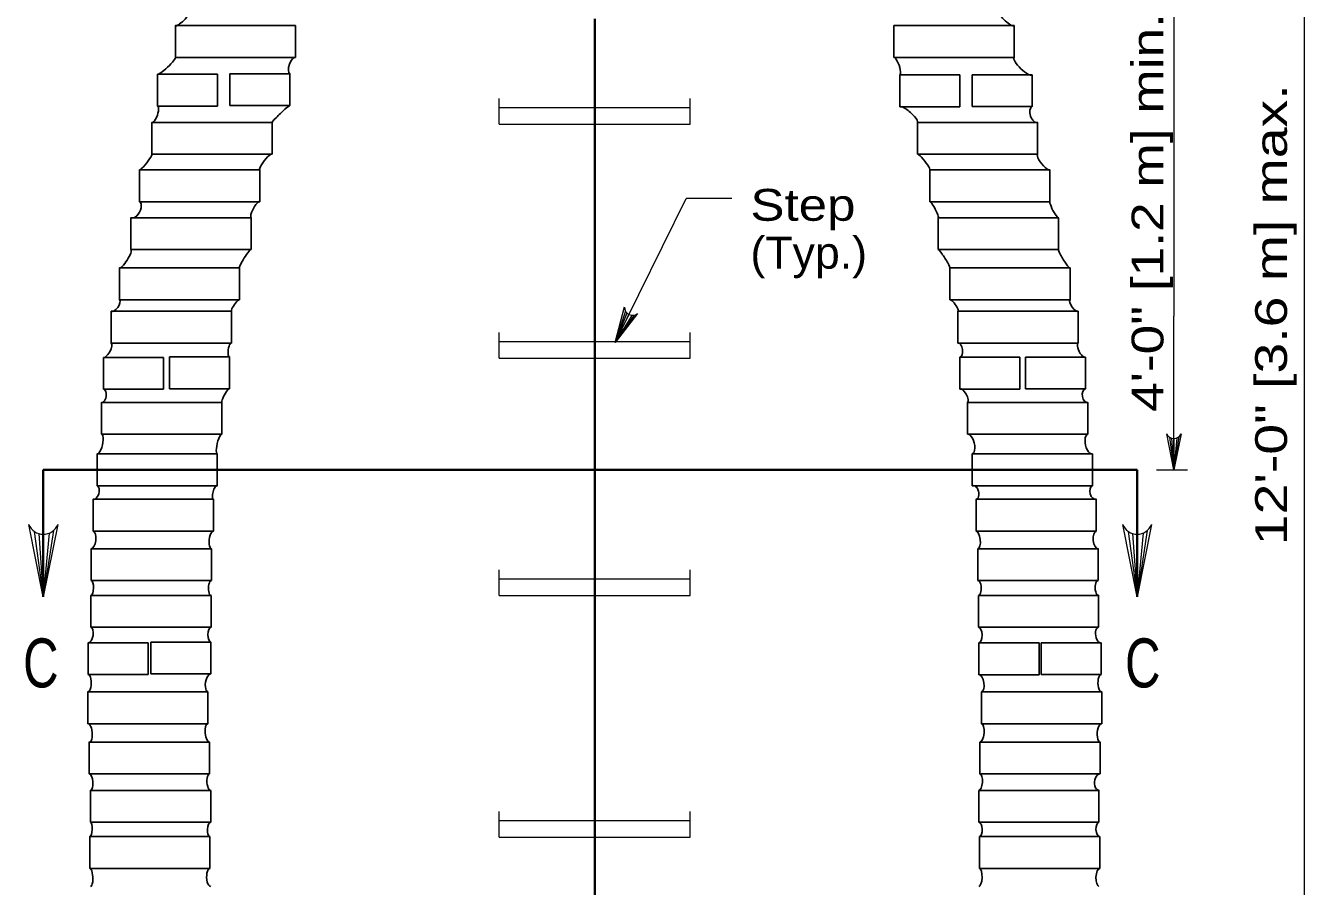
# Model space of a CAD drawing. Extents: x 1083.1 to 1117.1, y 697.4 to 741.4.
# Drawn here: x 1087.43 to 1093.7, y 732.34 to 736.56 of the extents above; entities that cross this region are included whole.
import ezdxf

# ---------------------------------------------------------------- set-up
doc = ezdxf.new("R2010")
doc.units = 0
doc.header["$LTSCALE"] = 0.062
doc.layers.add('1', color=7, linetype='Continuous', lineweight=13)

msp = doc.modelspace()

# ---------------------------------------------------------------- linework, layer by layer
at = {"layer": '1'}
for p, q in [((1093.70258, 733.89467), (1093.70258, 738.99733)), ((1093.06292, 738.25633), (1093.06292, 735.13425)), ((1089.75575, 736.07425), (1089.75575, 736.19958)), ((1089.75575, 736.15558), (1090.69217, 736.15558)), ((1090.69217, 736.07425), (1090.69217, 736.19958)), ((1089.75575, 736.07425), (1090.69217, 736.07425)), ((1090.32342, 735.00442), (1090.67242, 735.71092)), ((1090.89642, 735.71092), (1090.67242, 735.71092)), ((1090.37467, 735.15792), (1090.32342, 735.00442)), ((1090.38217, 735.14808), (1090.32342, 735.00442)), ((1090.39158, 735.14158), (1090.32342, 735.00442)), ((1090.41775, 735.13858), (1090.32342, 735.00442)), ((1090.40575, 735.13767), (1090.32342, 735.00442)), ((1093.06292, 734.38058), (1093.06292, 735.13425)), ((1089.75575, 734.92767), (1089.75575, 735.05292)), ((1090.69217, 734.92767), (1090.69217, 735.05292)), ((1089.75575, 735.009), (1090.69217, 735.009)), ((1089.75575, 734.92767), (1090.69217, 734.92767)), ((1093.0405, 734.54083), (1093.06292, 734.38058)), ((1093.05158, 734.53542), (1093.06292, 734.38058)), ((1093.08775, 734.54275), (1093.06292, 734.38058)), ((1093.07733, 734.53658), (1093.06292, 734.38058)), ((1093.06292, 734.53375), (1093.06292, 734.38058)), ((1092.97708, 734.38058), (1093.12975, 734.38058)), ((1087.47642, 734.07933), (1087.52125, 733.75883)), ((1087.57083, 734.08308), (1087.52125, 733.75883)), ((1092.83792, 734.07925), (1092.88275, 733.75883)), ((1092.93233, 734.08308), (1092.88275, 733.75883)), ((1087.49867, 734.0685), (1087.52125, 733.75883)), ((1087.55008, 734.07083), (1087.52125, 733.75883)), ((1087.52125, 734.06517), (1087.52125, 733.75883)), ((1092.86017, 734.06842), (1092.88275, 733.75883)), ((1092.91158, 734.07083), (1092.88275, 733.75883)), ((1092.88275, 734.06517), (1092.88275, 733.75883)), ((1089.75575, 733.76483), (1089.75575, 733.89017)), ((1090.69217, 733.76483), (1090.69217, 733.89017)), ((1093.70258, 730.36367), (1093.70258, 733.89467)), ((1089.75575, 733.84625), (1090.69217, 733.84625)), ((1089.75575, 733.76483), (1090.69217, 733.76483)), ((1089.75575, 732.58133), (1089.75575, 732.70667)), ((1090.69217, 732.58133), (1090.69217, 732.70667)), ((1089.75575, 732.66267), (1090.69217, 732.66267)), ((1089.75575, 732.58133), (1090.69217, 732.58133))]:
    msp.add_line(p, q, dxfattribs=at)
at = {"layer": '1', "lineweight": 35}
for p, q in [((1090.224, 730.90125), (1090.224, 736.59083)), ((1087.52125, 734.38058), (1087.52125, 733.75883)), ((1088.37375, 734.38058), (1087.52125, 734.38058)), ((1092.88275, 734.38058), (1092.88275, 733.75883))]:
    msp.add_line(p, q, dxfattribs=at)
at = {"layer": '1', "lineweight": 25}
for p, q in [((1088.75775, 736.40167), (1088.75775, 736.55758)), ((1091.69017, 736.40167), (1091.69017, 736.55758)), ((1088.1685, 736.40167), (1088.75775, 736.40167)), ((1092.27942, 736.40167), (1091.69017, 736.40167)), ((1088.37525, 736.31933), (1088.08067, 736.31933)), ((1088.08067, 736.16333), (1088.08067, 736.31933)), ((1088.37525, 736.16333), (1088.37525, 736.31933)), ((1088.72992, 736.32142), (1088.43525, 736.32142)), ((1088.43525, 736.16542), (1088.43525, 736.32142)), ((1088.72992, 736.16542), (1088.72992, 736.32142)), ((1092.014, 736.31575), (1091.71942, 736.31575)), ((1091.71942, 736.15975), (1091.71942, 736.31575)), ((1092.014, 736.15975), (1092.014, 736.31575)), ((1092.36842, 736.31675), (1092.07375, 736.31675)), ((1092.07375, 736.16083), (1092.07375, 736.31675)), ((1092.36842, 736.16083), (1092.36842, 736.31675)), ((1088.37525, 736.16333), (1088.08067, 736.16333)), ((1088.72992, 736.16542), (1088.43525, 736.16542)), ((1092.014, 736.15975), (1091.71942, 736.15975)), ((1092.36842, 736.16083), (1092.07375, 736.16083)), ((1088.64233, 735.92692), (1088.64233, 736.08292)), ((1091.80558, 735.92692), (1091.80558, 736.08292)), ((1088.05317, 735.92692), (1088.64233, 735.92692)), ((1092.39483, 735.92692), (1091.80558, 735.92692)), ((1088.58183, 735.69458), (1088.58183, 735.85058)), ((1091.86608, 735.69458), (1091.86608, 735.85058)), ((1087.99258, 735.69458), (1088.58183, 735.69458)), ((1092.45533, 735.69458), (1091.86608, 735.69458)), ((1088.54025, 735.46025), (1088.54025, 735.61625)), ((1091.90775, 735.46025), (1091.90775, 735.61625)), ((1087.951, 735.46025), (1088.54025, 735.46025)), ((1092.497, 735.46025), (1091.90775, 735.46025)), ((1088.48342, 735.21392), (1088.48342, 735.36992)), ((1091.9645, 735.21392), (1091.9645, 735.36992)), ((1087.89425, 735.21392), (1088.48342, 735.21392)), ((1092.55375, 735.21392), (1091.9645, 735.21392)), ((1088.44375, 735.00158), (1088.44375, 735.15758)), ((1092.00425, 735.00158), (1092.00425, 735.15758)), ((1087.8545, 735.00158), (1088.44375, 735.00158)), ((1092.5935, 735.00158), (1092.00425, 735.00158)), ((1088.11075, 734.9315), (1087.81617, 734.9315)), ((1087.81617, 734.77558), (1087.81617, 734.9315)), ((1088.11075, 734.77558), (1088.11075, 734.9315)), ((1088.43408, 734.934), (1088.1395, 734.934)), ((1088.1395, 734.778), (1088.1395, 734.934)), ((1088.43408, 734.778), (1088.43408, 734.934)), ((1092.30825, 734.93242), (1092.01367, 734.93242)), ((1092.01367, 734.77642), (1092.01367, 734.93242)), ((1092.30825, 734.77642), (1092.30825, 734.93242)), ((1092.62958, 734.93358), (1092.335, 734.93358)), ((1092.335, 734.77758), (1092.335, 734.93358)), ((1092.62958, 734.77758), (1092.62958, 734.93358)), ((1088.11075, 734.77558), (1087.81617, 734.77558)), ((1088.43408, 734.778), (1088.1395, 734.778)), ((1092.30825, 734.77642), (1092.01367, 734.77642)), ((1092.62958, 734.77767), (1092.335, 734.77767)), ((1088.39642, 734.555), (1088.39642, 734.71092)), ((1092.0515, 734.555), (1092.0515, 734.71092)), ((1087.80717, 734.555), (1088.39642, 734.555)), ((1092.64075, 734.555), (1092.0515, 734.555)), ((1088.37375, 734.30258), (1088.37375, 734.45858)), ((1092.07425, 734.30258), (1092.07425, 734.45858)), ((1087.7845, 734.30258), (1088.37375, 734.30258)), ((1092.66342, 734.30258), (1092.07425, 734.30258)), ((1088.35483, 734.08033), (1088.35483, 734.23625)), ((1092.09317, 734.08033), (1092.09317, 734.23625)), ((1087.76558, 734.08033), (1088.35483, 734.08033)), ((1092.68242, 734.08033), (1092.09317, 734.08033)), ((1088.34533, 733.83792), (1088.34533, 733.99392)), ((1092.10258, 733.83792), (1092.10258, 733.99392)), ((1087.75608, 733.83792), (1088.34533, 733.83792)), ((1092.69183, 733.83792), (1092.10258, 733.83792)), ((1088.3435, 733.60958), (1088.3435, 733.76558)), ((1092.1045, 733.60958), (1092.1045, 733.76558)), ((1087.75425, 733.60958), (1088.3435, 733.60958)), ((1092.69375, 733.60958), (1092.1045, 733.60958)), ((1088.03592, 733.53383), (1087.74125, 733.53383)), ((1087.74125, 733.37783), (1087.74125, 733.53383)), ((1088.03592, 733.37783), (1088.03592, 733.53383)), ((1088.34242, 733.53633), (1088.04783, 733.53633)), ((1088.04783, 733.38042), (1088.04783, 733.53633)), ((1088.34242, 733.38042), (1088.34242, 733.53633)), ((1092.40208, 733.5325), (1092.1075, 733.5325)), ((1092.1075, 733.3765), (1092.1075, 733.5325)), ((1092.40208, 733.3765), (1092.40208, 733.5325)), ((1092.707, 733.53317), (1092.41242, 733.53317)), ((1092.41242, 733.37725), (1092.41242, 733.53317)), ((1092.707, 733.37717), (1092.707, 733.53317)), ((1088.03592, 733.37792), (1087.74125, 733.37792)), ((1088.34242, 733.38042), (1088.04783, 733.38042)), ((1092.40208, 733.3765), (1092.1075, 733.3765)), ((1092.707, 733.37725), (1092.41242, 733.37725)), ((1088.32833, 733.13692), (1088.32833, 733.29292)), ((1092.11958, 733.13692), (1092.11958, 733.29292)), ((1087.73908, 733.13692), (1088.32833, 733.13692)), ((1092.70883, 733.13692), (1092.11958, 733.13692)), ((1088.33592, 732.89058), (1088.33592, 733.04658)), ((1092.11208, 732.89058), (1092.11208, 733.04658)), ((1087.74667, 732.89058), (1088.33592, 732.89058)), ((1092.70133, 732.89058), (1092.11208, 732.89058)), ((1088.34158, 732.65425), (1088.34158, 732.81025)), ((1092.10642, 732.65425), (1092.10642, 732.81025)), ((1087.75233, 732.65425), (1088.34158, 732.65425)), ((1092.69558, 732.65425), (1092.10642, 732.65425)), ((1088.33775, 732.42792), (1088.33775, 732.58392)), ((1092.11017, 732.42792), (1092.11017, 732.58392)), ((1087.74858, 732.42792), (1088.33775, 732.42792)), ((1092.69942, 732.42792), (1092.11017, 732.42792))]:
    msp.add_line(p, q, dxfattribs=at)
for points in [[(1088.1685, 736.40167), (1088.1685, 736.55758), (1088.75775, 736.55758)], [(1092.27942, 736.40167), (1092.27942, 736.55758), (1091.69017, 736.55758)], [(1088.05317, 735.92692), (1088.05317, 736.08292), (1088.64233, 736.08292)], [(1092.39483, 735.92692), (1092.39483, 736.08292), (1091.80558, 736.08292)], [(1087.99258, 735.69458), (1087.99258, 735.85058), (1088.58183, 735.85058)], [(1092.45533, 735.69458), (1092.45533, 735.85058), (1091.86608, 735.85058)], [(1087.951, 735.46025), (1087.951, 735.61625), (1088.54025, 735.61625)], [(1092.497, 735.46025), (1092.497, 735.61625), (1091.90775, 735.61625)], [(1087.89425, 735.21392), (1087.89425, 735.36992), (1088.48342, 735.36992)], [(1092.55375, 735.21392), (1092.55375, 735.36992), (1091.9645, 735.36992)], [(1087.8545, 735.00158), (1087.8545, 735.15758), (1088.44375, 735.15758)], [(1092.5935, 735.00158), (1092.5935, 735.15758), (1092.00425, 735.15758)], [(1087.80717, 734.555), (1087.80717, 734.71092), (1088.39642, 734.71092)], [(1092.64075, 734.555), (1092.64075, 734.71092), (1092.0515, 734.71092)], [(1087.7845, 734.30258), (1087.7845, 734.45858), (1088.37375, 734.45858)], [(1092.66342, 734.30258), (1092.66342, 734.45858), (1092.07425, 734.45858)], [(1087.76558, 734.08033), (1087.76558, 734.23625), (1088.35483, 734.23625)], [(1092.68242, 734.08033), (1092.68242, 734.23625), (1092.09317, 734.23625)], [(1087.75608, 733.83792), (1087.75608, 733.99392), (1088.34533, 733.99392)], [(1092.69183, 733.83792), (1092.69183, 733.99392), (1092.10258, 733.99392)], [(1087.75425, 733.60958), (1087.75425, 733.76558), (1088.3435, 733.76558)], [(1092.69375, 733.60958), (1092.69375, 733.76558), (1092.1045, 733.76558)], [(1087.73908, 733.13692), (1087.73908, 733.29292), (1088.32833, 733.29292)], [(1092.70883, 733.13692), (1092.70883, 733.29292), (1092.11958, 733.29292)], [(1087.74667, 732.89058), (1087.74667, 733.04658), (1088.33592, 733.04658)], [(1092.70133, 732.89058), (1092.70133, 733.04658), (1092.11208, 733.04658)], [(1087.75233, 732.65425), (1087.75233, 732.81025), (1088.34158, 732.81025)], [(1092.69558, 732.65425), (1092.69558, 732.81025), (1092.10642, 732.81025)], [(1087.74858, 732.42792), (1087.74858, 732.58392), (1088.33775, 732.58392)], [(1092.69942, 732.42792), (1092.69942, 732.58392), (1092.11017, 732.58392)]]:
    msp.add_lwpolyline(points, dxfattribs=at)
at = {"layer": '1'}
for points in [[(1090.43392, 735.14717), (1090.32342, 735.00442), (1090.3705, 735.17867)], [(1093.09833, 734.55758), (1093.06292, 734.38058), (1093.0275, 734.55758)], [(1087.59208, 734.11283), (1087.52125, 733.75883), (1087.4505, 734.11283)], [(1092.95358, 734.11283), (1092.88275, 733.75883), (1092.812, 734.11283)]]:
    msp.add_lwpolyline(points, dxfattribs=at)
at = {"layer": '1', "lineweight": 35}
msp.add_lwpolyline([(1092.88275, 734.38058), (1092.66342, 734.38058), (1088.37375, 734.38058)], dxfattribs=at)
at = {"layer": '1'}
for centre, radius, start, end in [((1090.40854, 735.17574), 0.0382, 175.64712, 311.47324), ((1093.0629, 734.57189), 0.0382, 202.08782, 337.91395), ((1087.52121, 734.14143), 0.0764, 202.08782, 337.91395), ((1092.88271, 734.14139), 0.0764, 202.08782, 337.91395)]:
    msp.add_arc(centre, radius, start, end, dxfattribs=at)
at = {"layer": '1', "lineweight": 25}
for centre, major_axis, ratio, start_param, end_param in [((1088.20353, 736.59077), (0.03491, 0.03328), 0.214158, 3.1288563, 6.2704489), ((1092.24442, 736.59077), (-0.03485, 0.03334), 0.271388, 0.0166254, 3.158218), ((1088.1246, 736.36047), (0.04388, 0.04122), 0.144657, 3.1332208, 6.2748134), ((1088.74383, 736.36151), (-0.01364, -0.04023), 0.407354, 3.1235301, 6.2651227), ((1091.70479, 736.35868), (0.0145, -0.04299), 0.258559, 0.0100835, 3.1516762), ((1092.32391, 736.35921), (-0.0443, 0.04264), 0.279847, 0.0172411, 3.1588337), ((1088.0669, 736.12314), (-0.01358, -0.0403), 0.335589, 6.2693556, 9.4109483), ((1088.68613, 736.12417), (-0.04376, -0.04127), 0.064605, 3.137914, 6.2795067), ((1091.76249, 736.12135), (0.04296, -0.03859), 0.241358, 0.0144197, 3.1560124), ((1092.38161, 736.12187), (-0.01262, 0.03917), 0.542882, 0.0279504, 3.169543), ((1088.02286, 735.88876), (0.03023, 0.03822), 0.136372, 3.1337805, 6.2753732), ((1088.6121, 735.88876), (-0.03017, -0.03827), 0.209512, 3.1292724, 6.2708651), ((1091.83585, 735.88876), (0.03022, -0.03823), 0.155778, 0.0089758, 3.1505685), ((1092.42509, 735.88876), (-0.03009, 0.03834), 0.282428, 0.0172571, 3.1588498), ((1087.97178, 735.65543), (0.02002, 0.03962), 0.541644, 3.1041747, 6.2457674), ((1088.56102, 735.65543), (-0.02067, -0.03927), 0.264991, 3.1276914, 6.2692841), ((1091.88693, 735.65543), (0.02077, -0.03921), 0.149207, 0.0074425, 3.1490352), ((1092.47617, 735.65543), (-0.02076, 0.03922), 0.156228, 0.00781, 3.1494027), ((1087.92259, 735.41508), (0.02825, 0.04528), 0.223655, 3.1291999, 6.2707925), ((1088.51183, 735.41508), (-0.02834, -0.04523), 0.13218, 3.1345117, 6.2761043), ((1091.93612, 735.41508), (0.02835, -0.04521), 0.098077, 0.0052123, 3.146805), ((1092.52535, 735.41508), (-0.02835, 0.04522), 0.114707, 0.006118, 3.1477107), ((1087.87435, 735.18575), (0.01952, 0.02843), 0.429767, 3.112728, 6.2543206), ((1088.46359, 735.18575), (-0.0198, -0.02822), 0.206426, 3.1297914, 6.2713841), ((1091.98436, 735.18575), (0.01976, -0.02825), 0.258713, 0.0151769, 3.1567696), ((1092.5736, 735.18575), (-0.01967, 0.02832), 0.336532, 0.020776, 3.1623686), ((1087.83531, 734.96658), (0.01897, 0.03516), 0.327378, 3.123429, 6.2650216), ((1088.43892, 734.96779), (-0.00474, -0.03384), 0.324121, 3.1355093, 6.277102), ((1092.00893, 734.967), (0.0045, -0.03465), 0.523289, 0.0116007, 3.1531933), ((1092.61153, 734.9676), (-0.01779, 0.03418), 0.380519, 0.0217078, 3.1633005), ((1087.81166, 734.74326), (0.00425, 0.03236), 0.53803, 3.1292062, 6.2707989), ((1088.41527, 734.74448), (-0.01879, -0.03357), 0.173986, 3.1325933, 6.274186), ((1092.03258, 734.74368), (0.01867, -0.03291), 0.376867, 0.022341, 3.1639336), ((1092.63517, 734.74429), (-0.00516, 0.03342), 0.625583, 0.0201562, 3.1617488), ((1087.79584, 734.50678), (0.01121, 0.04824), 0.311835, 3.1323355, 6.2739282), ((1088.38508, 734.50678), (0.01127, 0.04822), 0.238035, 6.2764231, 9.4180158), ((1092.06287, 734.50678), (0.01104, -0.04828), 0.44347, 0.0147954, 3.1563881), ((1092.6521, 734.50678), (-0.011, 0.04829), 0.462292, 0.0157578, 3.1573505), ((1087.77503, 734.26944), (0.00902, 0.03331), 0.545405, 3.1170644, 6.2586571), ((1088.36427, 734.26944), (-0.00933, -0.03322), 0.336345, 3.1296141, 6.2712067), ((1092.08368, 734.26944), (0.00865, -0.03341), 0.65918, 0.0368482, 3.1784409), ((1092.67291, 734.26944), (-0.00883, 0.03336), 0.611305, 0.0308457, 3.1724383), ((1087.76084, 734.0371), (0.00463, 0.04321), 0.395652, 3.1354665, 6.2770591), ((1088.35008, 734.0371), (-0.00465, -0.0432), 0.355132, 3.1362853, 6.277878), ((1092.09787, 734.0371), (0.00464, -0.0432), 0.361488, 0.0054302, 3.1470228), ((1092.6871, 734.0371), (-0.00457, 0.04321), 0.463687, 0.0077136, 3.1493062), ((1087.75517, 733.80177), (0.00093, 0.03619), 0.339333, 3.1403824, 6.281975), ((1088.3444, 733.80177), (-0.00093, -0.03619), 0.385436, 3.140164, 6.2817567), ((1092.10354, 733.80177), (0.00092, -0.03619), 0.416071, 0.0015877, 3.1431804), ((1092.69278, 733.80176), (-0.00092, 0.03619), 0.442959, 0.0017389, 3.1433316), ((1087.74776, 733.57172), (0.00627, 0.03793), 0.451649, 3.1302607, 6.2718533), ((1088.34295, 733.57299), (-0.00049, -0.03664), 0.404629, 3.1407844, 6.282377), ((1092.10598, 733.57105), (0.00146, -0.03858), 0.431241, 0.0024799, 3.1440725), ((1092.70038, 733.5714), (-0.00631, 0.03829), 0.551578, 0.016132, 3.1577247), ((1087.74019, 733.33539), (0.00108, 0.04249), 0.377199, 3.1402157, 6.2818084), ((1088.33539, 733.33665), (-0.00687, -0.04379), 0.431696, 3.1315357, 6.2731284), ((1092.11355, 733.33471), (0.0059, -0.04184), 0.435487, 0.0092134, 3.150806), ((1092.70794, 733.33506), (-0.00089, 0.04216), 0.413769, 0.0013076, 3.1429003), ((1087.74287, 733.09174), (0.0037, -0.04521), 0.400858, 0.0047949, 3.1463876), ((1088.33211, 733.09175), (-0.0037, 0.04521), 0.39708, 0.0047328, 3.1463254), ((1092.11584, 733.09175), (0.00372, 0.0452), 0.36206, 3.1374093, 6.2790019), ((1092.70508, 733.09174), (-0.0037, -0.04521), 0.399778, 3.1368155, 6.2784082), ((1087.74949, 732.8504), (0.00279, -0.04019), 0.361167, 0.0035249, 3.1451175), ((1088.33873, 732.8504), (-0.00278, 0.0402), 0.378539, 0.0037498, 3.1453425), ((1092.10922, 732.8504), (0.00278, 0.04019), 0.368842, 3.1379693, 6.2795619), ((1092.69845, 732.8504), (-0.00264, -0.0402), 0.606686, 3.1334441, 6.2750368), ((1087.75044, 732.61907), (-0.00187, -0.03519), 0.307162, 6.280988, 9.4225806), ((1088.33968, 732.61907), (0.00185, 0.03519), 0.404304, 6.2800541, 9.4216467), ((1092.10827, 732.61907), (0.00184, -0.03519), 0.42781, 0.0033919, 3.1449845), ((1092.69751, 732.61907), (-0.00183, 0.03519), 0.471573, 0.0039281, 3.1455207), ((1087.75044, 732.38373), (0.00187, -0.0442), 0.307813, 0.0017551, 3.1433478), ((1088.33967, 732.38373), (0.00185, -0.0442), 0.403909, 3.1440839, 6.2856766), ((1092.10827, 732.38373), (0.00187, 0.0442), 0.320957, 3.1397455, 6.2813381), ((1092.69751, 732.38373), (-0.00185, -0.0442), 0.379685, 3.1393036, 6.2808962)]:
    msp.add_ellipse(centre, major_axis=major_axis, ratio=ratio, start_param=start_param, end_param=end_param, dxfattribs=at)

# ---------------------------------------------------------------- texts
at = {"layer": '1'}
for s, width, p in [('4\'-0" [1.2 m] min. corbel', 1.25, (1093.01158, 734.66483)), ('12\'-0" [3.6 m] max.', 1.3, (1093.61717, 734.01125))]:
    msp.add_text(s, height=0.156, rotation=90, dxfattribs=dict(at, width=width)).set_placement(p)
for s, height, width, p in [('Step', 0.156, 1.2, (1090.98708, 735.60117)), ('(Typ.)', 0.156, 1.05, (1090.98708, 735.3665)), ('C', 0.24, 0.75, (1087.42208, 733.31458)), ('C', 0.24, 0.75, (1092.82325, 733.31458))]:
    msp.add_text(s, height=height, dxfattribs=dict(at, width=width)).set_placement(p)

doc.saveas('drawing.dxf')
